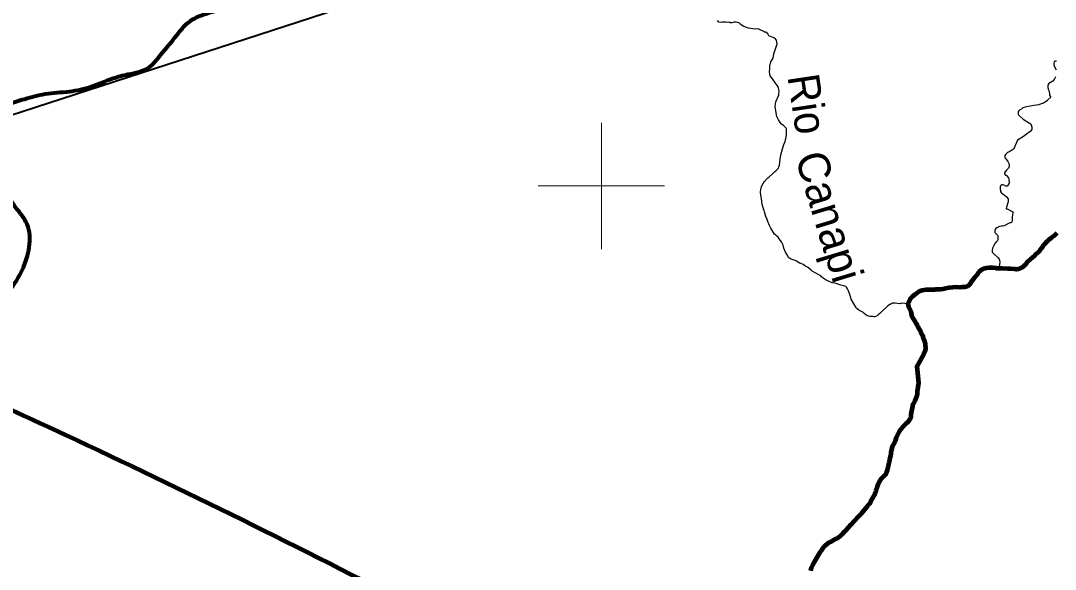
# Model space of a CAD drawing. Extents: x 553962 to 842807, y 8883888 to 9032388.
# Drawn here: x 640806 to 657184, y 8968932 to 8977616 of the extents above; entities that cross this region are included whole.
import ezdxf
from ezdxf.enums import TextEntityAlignment as Align

# ---------------------------------------------------------------- set-up
doc = ezdxf.new("R2010")
doc.units = 0
doc.header["$LTSCALE"] = 200
for name, color, linetype, lineweight in [('12', 7, 'Continuous', 25), ('2', 7, 'Continuous', 13), ('24', 7, 'Continuous', 25), ('50', 7, 'Continuous', 80), ('9', 7, 'Continuous', 90)]:
    doc.layers.add(name, color=color, linetype=linetype, lineweight=lineweight)
doc.layers.add('49', color=7, linetype='Continuous')

msp = doc.modelspace()

# ---------------------------------------------------------------- linework, layer by layer
at = {"layer": '12', "lineweight": 40}
msp.add_line((636526.5, 8974783.6), (662912, 8983353), dxfattribs=at)
at = {"layer": '2'}
for p, q in [((650000, 8974000), (650000, 8976000)), ((649000, 8975000), (651000, 8975000))]:
    msp.add_line(p, q, dxfattribs=at)
at = {"layer": '24'}
for p, q in [((655116.6, 8973422.7), (655117, 8973424.3)), ((654851.3, 8973132), (654755.7, 8973142.7))]:
    msp.add_line(p, q, dxfattribs=at)
for points in [[(652771.6, 8977307.6), (652743.6, 8977336.7), (652700, 8977355.6), (652648.8, 8977376.5), (652631.7, 8977406.9), (652599.1, 8977434.4), (652582.3, 8977435.4), (652567.8, 8977444.9), (652514, 8977471.5), (652479.8, 8977484.8), (652430.5, 8977481), (652391.1, 8977486.8), (652363.3, 8977492), (652326.1, 8977499.9), (652255.9, 8977522.7), (652202.8, 8977555), (652189.5, 8977577.8), (652130.7, 8977591.1), (652098.4, 8977593), (652062.3, 8977583.5), (652039.6, 8977583.5), (652020.6, 8977593), (651997.8, 8977587.3), (651961.8, 8977593), (651916.2, 8977594.9), (651899.2, 8977589.2), (651855.5, 8977591.1), (651834.4, 8977616.2)], [(652799.8, 8975280.4), (652809.8, 8975302.2), (652816.1, 8975328.3), (652822.4, 8975374.6), (652826.9, 8975422.5), (652839.8, 8975493.2), (652864.5, 8975587.5), (652888.2, 8975655.6), (652908, 8975704.5), (652925.9, 8975773.4), (652929.4, 8975820.5), (652930.5, 8975902.1), (652923, 8975914.4), (652902.1, 8975937.5), (652881.4, 8975957.1), (652852.2, 8975978.9), (652827.9, 8976005.5), (652801.9, 8976045.7), (652783.3, 8976090.1), (652777.5, 8976093.8), (652748.7, 8976257.8), (652752.2, 8976297.8), (652759.6, 8976332.9), (652774.2, 8976369.2), (652784.3, 8976387.2), (652805.5, 8976443.3), (652809.5, 8976460.7), (652811.3, 8976493), (652801.1, 8976555.8), (652798.8, 8976558), (652796.5, 8976566.6), (652771.4, 8976603.6), (652757.2, 8976628.1), (652709.4, 8976696.7), (652669.3, 8976741.1), (652663.9, 8976773), (652657.8, 8976807.6), (652663.9, 8976859.5), (652664.9, 8976895.8), (652682.2, 8976964.3), (652718.6, 8977021.2), (652730, 8977089.5), (652778.6, 8977249)], [(652778.6, 8977249), (652777.9, 8977274.4), (652771.6, 8977307.6)], [(657200.6, 8976974.4), (657181.2, 8976975.7), (657176.4, 8976974.4), (657164.7, 8976965.5), (657159.4, 8976934.9), (657159.4, 8976922.3), (657172.8, 8976885.3), (657195, 8976838.1)], [(657133.7, 8976651.6), (657080.2, 8976620), (657066.2, 8976597.4), (657063.1, 8976576.8), (657066.3, 8976556.2), (657072.5, 8976533.5), (657080.9, 8976509.9), (657090.5, 8976462.8), (657091, 8976439.3), (657110, 8976410.1), (657110.9, 8976406.4), (657067.4, 8976361), (657056.2, 8976354.8), (657053.5, 8976348.9), (657031.1, 8976329.9), (657013.6, 8976321.3), (656995.6, 8976309.4), (656979.2, 8976303.3), (656959.2, 8976299.6), (656920.6, 8976285.8), (656884.5, 8976276.8), (656845.1, 8976271.2), (656729.4, 8976250.9), (656707.8, 8976249), (656672.3, 8976234.3), (656651.5, 8976222.8), (656618, 8976199.7), (656600.5, 8976181.9), (656595.8, 8976166.3), (656594.8, 8976146.6), (656595.7, 8976138.4), (656602.4, 8976126.5), (656615.7, 8976111), (656677.7, 8976057.2), (656776.5, 8975994.6), (656782.5, 8975993.7), (656799.6, 8975973.9), (656803.7, 8975967.1), (656814.1, 8975929.4), (656813.1, 8975895.9), (656791.5, 8975865.6), (656785.6, 8975862.2), (656783.8, 8975858), (656775.5, 8975856.3), (656772.4, 8975851.8), (656742.2, 8975832.4), (656721.1, 8975813.8), (656679, 8975783.2), (656609.4, 8975739.2), (656588, 8975723), (656553.5, 8975648.5), (656550.6, 8975639.1), (656544.7, 8975630.5), (656542.4, 8975621.5), (656520.2, 8975584), (656507.8, 8975571.5), (656503.7, 8975569.7), (656500.5, 8975566.2), (656496.9, 8975565.1), (656495.3, 8975562.1), (656486.8, 8975559.7), (656479.1, 8975553.8), (656468.9, 8975552.5), (656445.8, 8975536.4), (656445.8, 8975536.4)], [(657185.6, 8976725.5), (657177.3, 8976704.9), (657165.5, 8976683.5), (657144.4, 8976659), (657138.5, 8976657.5), (657133.7, 8976651.6)], [(656445.8, 8975536.4), (656428.1, 8975527.1), (656412.7, 8975513.8), (656400.9, 8975501.1), (656386.7, 8975481.1), (656383.9, 8975464.5), (656385.2, 8975443.3), (656398.8, 8975427.1), (656422.7, 8975403.9), (656434, 8975387.3), (656444.5, 8975366.6), (656451.2, 8975343.8), (656452.2, 8975307.7), (656444.4, 8975279.3), (656420.2, 8975258.8), (656406.9, 8975244.3), (656382, 8975208.4), (656379.8, 8975191.2), (656391.2, 8975173.8), (656397, 8975172), (656400.5, 8975168.9), (656408.8, 8975165.1), (656442.9, 8975127.3), (656450.2, 8975105.1), (656451, 8975049), (656444.2, 8975024.3), (656423.6, 8974996.6), (656411.6, 8974995.5), (656402.2, 8974996.5), (656392.2, 8975002.6), (656384.2, 8975004.6), (656371.7, 8975013.2), (656353.6, 8975017.8), (656334.6, 8975017.5), (656320.6, 8975007.7), (656317.6, 8975003.5), (656311.8, 8974985.1)], [(654755.7, 8973142.7), (654720.6, 8973132.1), (654647.5, 8973144.9), (654604.9, 8973142), (654598.8, 8973140.5), (654534.6, 8973104.9), (654437.3, 8973012.6), (654419.5, 8972998.8), (654403.8, 8972979.2), (654381.6, 8972957.8), (654363, 8972946.1), (654335.2, 8972931.4), (654326.4, 8972929.3), (654308.8, 8972928.4), (654287.9, 8972933.5), (654250.2, 8972934.8), (654229.3, 8972940.7), (654192.4, 8972956.2), (654152.5, 8972986.8), (654147.8, 8972992.5), (654142.1, 8972995.3), (654139, 8973001.3), (654076, 8973035.9), (654041.5, 8973060), (654027.3, 8973074.1), (654028.3, 8973079.5), (653955, 8973206), (653948.8, 8973231.1), (653931.5, 8973279.1), (653918, 8973324.5), (653906.3, 8973348.1), (653892.5, 8973371.7), (653880.9, 8973398.6), (653873.4, 8973402.2), (653869.2, 8973406.6), (653838.8, 8973418.7), (653790.9, 8973428.7), (653697.5, 8973459.4), (653649.6, 8973468.4), (653604, 8973484.9), (653582.4, 8973495.6), (653556.1, 8973510.9), (653509.5, 8973541.4), (653482.9, 8973561.9), (653470.5, 8973577.6), (653442.6, 8973592.3), (653395.4, 8973620.1), (653335.2, 8973650.9), (653328.8, 8973657.6), (653317.1, 8973665.3), (653282.9, 8973700.4), (653261.2, 8973715), (653237, 8973727.3), (653213.3, 8973743.3), (653191.4, 8973755.3), (653143.5, 8973777.1), (653134.4, 8973779.3), (653111.9, 8973795.2), (653085.1, 8973811.8), (653065.5, 8973821.4), (653019.2, 8973837.3), (653002.9, 8973840.6), (652981, 8973851.6), (652965.9, 8973864.6), (652937, 8973909.3), (652911.1, 8973953), (652887.5, 8974017.3), (652874.5, 8974060.1), (652864.8, 8974083.7), (652850.2, 8974112.8), (652813.3, 8974163.9), (652794.5, 8974187.8), (652771, 8974210.2), (652753.5, 8974223.6), (652741.1, 8974236.2), (652681.1, 8974329.2), (652660, 8974375.6), (652651, 8974399.9), (652639.3, 8974423.5), (652623.5, 8974469.8), (652603.2, 8974516.9), (652579.3, 8974588.4), (652572.8, 8974612), (652562.8, 8974637.3), (652546.2, 8974706.2), (652532.2, 8974799.6), (652526.8, 8974824.9), (652519.2, 8974897.6), (652518.3, 8974918.3), (652521.3, 8974941), (652527.4, 8974967.1), (652535.4, 8974989), (652558, 8975036.1), (652577.2, 8975063.9), (652631.7, 8975125.9), (652648.1, 8975141.2), (652704.5, 8975187.2), (652741, 8975221.5), (652762.8, 8975244.2), (652783.3, 8975259.7), (652799.8, 8975280.4)], [(656311.8, 8974985.1), (656309.9, 8974965.4), (656310.9, 8974936.3), (656314.2, 8974931), (656318.5, 8974912), (656333.2, 8974887.1), (656339.6, 8974883.1), (656344.1, 8974878.5), (656345.9, 8974874.7), (656352.9, 8974872.7), (656357, 8974868.2), (656372.6, 8974857.7), (656410.2, 8974827.3), (656435.2, 8974796.3), (656440.2, 8974762.4), (656440.3, 8974749.1), (656410.3, 8974666), (656407.6, 8974643.7), (656410, 8974639.2), (656419.4, 8974636), (656511, 8974591.7), (656507.5, 8974524.4), (656501.5, 8974515), (656499.2, 8974456.9), (656494.7, 8974426.9), (656479.6, 8974416.5), (656466.4, 8974413.5), (656443.7, 8974405.2), (656396.6, 8974380.7), (656373, 8974370.1), (656349.5, 8974365.7), (656325.9, 8974363.3), (656300.7, 8974356.3), (656256.1, 8974338), (656235.1, 8974319.4), (656224.5, 8974294.9), (656226, 8974270.5), (656228.6, 8974263.7), (656258.3, 8974232.1), (656265, 8974227.3), (656269.2, 8974222.2), (656273.4, 8974202.8), (656276.5, 8974180.1), (656276.6, 8974148.4), (656268.5, 8974134.2), (656264, 8974130.4), (656262.3, 8974125), (656257.6, 8974123.2), (656253.4, 8974116.8), (656244.1, 8974109.9), (656235.6, 8974096.1), (656229.8, 8974092), (656209.8, 8974056.4), (656189, 8974012.7), (656183.6, 8973985.6), (656184.6, 8973963), (656186.9, 8973950), (656191.3, 8973947.8), (656199.2, 8973934.2), (656213.7, 8973918.7), (656274.2, 8973865.6), (656294.1, 8973843.5), (656302.2, 8973822.7), (656307.8, 8973793.6), (656289.8, 8973694.9)]]:
    msp.add_lwpolyline(points, dxfattribs=at)
at = {"layer": '24', "lineweight": 53}
for points in [[(657210.5, 8974250), (657181.7, 8974226.4), (657161.9, 8974207.7), (657140, 8974192), (657118.9, 8974173.4), (657078.2, 8974140.8), (657056.3, 8974119.3), (657035, 8974103.2), (657016, 8974086.2), (656999.6, 8974063.5), (656982.9, 8974036.6), (656963.3, 8974017.4), (656946, 8973988.7), (656926.4, 8973964.7), (656902.1, 8973940.5), (656874.4, 8973917.8), (656856.7, 8973895.3), (656791.9, 8973840.8)], [(656791.9, 8973840.8), (656791.8, 8973840.8), (656728.6, 8973781.9), (656729.8, 8973775.9), (656716.7, 8973763.4), (656647.1, 8973704.9), (656615.1, 8973689.9), (656598.4, 8973684.2), (656598.4, 8973684.2), (656567.2, 8973679.3), (656556.3, 8973683.2), (656536.3, 8973682.5), (656475.8, 8973689.6), (656432.2, 8973686.7), (656347.3, 8973694), (656260.8, 8973695.2), (656240.2, 8973697.3)], [(656240.2, 8973697.3), (656197.4, 8973704.6), (656175.9, 8973703.8), (656133.1, 8973704.7), (656090.3, 8973699.3), (656067.2, 8973694.6), (656047.4, 8973688.6), (656026.8, 8973679.3), (655983.7, 8973648.4), (655968.2, 8973630.5), (655940.3, 8973590.2), (655926.4, 8973572.3), (655907.2, 8973551.6), (655857.4, 8973488), (655825.2, 8973435), (655819.5, 8973432.4), (655817.1, 8973428.1), (655813, 8973426.4), (655807.3, 8973421.2), (655797.6, 8973417.6), (655794, 8973413), (655766.8, 8973403.9), (655745.4, 8973399.7), (655722.2, 8973400.4), (655702.5, 8973398.4), (655680.3, 8973394.3), (655616.9, 8973396.2), (655501.2, 8973386.6), (655443.3, 8973378), (655404.8, 8973367.5), (655366.2, 8973362.1), (655326.8, 8973361.9), (655289.1, 8973358.7), (655269, 8973355.7), (655249.7, 8973356.6), (655212, 8973355.5), (655191.9, 8973353.5), (655154.1, 8973354.5), (655137.5, 8973353.6), (655077.8, 8973346), (655060.3, 8973342.2), (655039.3, 8973335.4), (655029.9, 8973329.2), (655023.6, 8973328.5), (655016.9, 8973321.8), (654963.5, 8973284.3), (654916.4, 8973246.2), (654900.8, 8973228.3), (654881.6, 8973201), (654851.3, 8973132), (654852.3, 8973113.8), (654858.7, 8973088.2), (654878.1, 8973056.9), (654895, 8973014.3), (654909.2, 8972953.2), (654915.3, 8972934.7), (654923.6, 8972916.2), (654947.3, 8972875.3), (654982.1, 8972819.3), (654996.2, 8972794.1), (655005.3, 8972774), (655014.6, 8972757.2), (655044.4, 8972710.5), (655053.7, 8972692), (655056.5, 8972676.5), (655080.1, 8972632.6), (655093.2, 8972594.1), (655109.8, 8972556.3), (655111.9, 8972544), (655121.8, 8972516.9), (655124, 8972498.5), (655124.2, 8972478.4), (655127.3, 8972439.8), (655123.7, 8972391.1), (655118.2, 8972380.4), (655102.9, 8972341.9), (654992.2, 8972144.1), (655019.8, 8971884.2), (654998.6, 8971745.3), (654995, 8971695.3), (654989.7, 8971685.4), (654957.7, 8971597.4), (654937.6, 8971556.5), (654925.2, 8971519.5), (654918.6, 8971481), (654907, 8971442.4), (654896.1, 8971382.9), (654895.8, 8971344.4), (654892, 8971324.4), (654883.1, 8971306.7), (654872.7, 8971291.8), (654840.1, 8971251.1), (654818.4, 8971232.1), (654818.4, 8971232.1), (654777.1, 8971189.8), (654713.1, 8971114), (654675.8, 8971041.8), (654665.8, 8971017.4), (654650.1, 8970966.2), (654641.7, 8970946), (654616.5, 8970899.6)], [(654616.5, 8970899.6), (654597.8, 8970850.8), (654585.3, 8970804.5), (654581.2, 8970781.8), (654578.8, 8970758.3), (654572.6, 8970734.7), (654560.7, 8970664), (654554.4, 8970640.4), (654550, 8970616.9), (654542.2, 8970591.6), (654533, 8970547), (654526.8, 8970523.4), (654524.2, 8970501.2), (654508.2, 8970458.4), (654499, 8970437.8), (654493.5, 8970429), (654477.7, 8970417.1), (654443, 8970382.2), (654421.1, 8970358.3), (654389.5, 8970306.2), (654379.5, 8970284), (654365, 8970242.8), (654351.1, 8970197.8), (654345.4, 8970173.5), (654336.8, 8970149.9), (654324.7, 8970123.6), (654288, 8970056.4), (654272.8, 8970031.9), (654254.6, 8969979.6), (654230.2, 8969960.2), (654218.1, 8969945.2), (654200.3, 8969917.9), (654115.1, 8969812.6), (654066, 8969768.5), (653998.5, 8969693.6), (653949.1, 8969634.7), (653875.5, 8969551.6), (653848.1, 8969526.1), (653826.1, 8969509.2), (653807.7, 8969485.9), (653788.8, 8969465.8), (653781.7, 8969461.6), (653774.9, 8969453.3), (653733.8, 8969425.9), (653708.2, 8969413.9), (653656.8, 8969380.9), (653631.1, 8969367), (653605.4, 8969356.1), (653579.7, 8969340.1), (653534.3, 8969303.2), (653514.9, 8969279.7), (653477.3, 8969225.2), (653456.6, 8969199.3), (653405, 8969106.7), (653344.1, 8969008.1), (653319.5, 8968956.7), (653307.6, 8968905.3)]]:
    msp.add_lwpolyline(points, dxfattribs=at)
at = {"layer": '50'}
msp.add_spline([(639219.5, 8972216.9), (639452.6, 8972345.4), (639566.1, 8972552.1), (639684.3, 8972733.3), (640073.1, 8972839), (640280.5, 8972922.2), (640428.6, 8973082.5), (640849.7, 8973711.5), (640889.8, 8974432.9), (640746.7, 8974633.5), (640599.2, 8974885), (640542.2, 8975124.8), (640537.6, 8975526.6), (640547.2, 8975862.1), (640623.3, 8976272.7), (640866.2, 8976375.7), (641194.3, 8976456.9), (641577.1, 8976496.6), (641925.3, 8976572.4), (642269.1, 8976704.3), (642501.4, 8976766.7), (642840, 8976878.3), (642993.1, 8977038.6), (643248.9, 8977349.8), (643488.9, 8977610.4), (643777.4, 8977738), (644100.5, 8977824.4), (644651.3, 8978008.9), (645197.8, 8978239.2), (645476.7, 8978402.6), (645653.3, 8978806.6), (645865.1, 8979215.1), (646221.3, 8979509.5), (646615.8, 8979665.9), (646766.4, 8979643.2), (647093, 8979617.7), (647304.4, 8979624.5), (647500.7, 8979631.6), (647581.3, 8979640.5), (647811.6, 8979776.6)], degree=3, dxfattribs=at)
at = {"layer": '9'}
for points in [[(657210.5, 8974250), (657181.7, 8974226.4), (657161.9, 8974207.7), (657140, 8974192), (657118.9, 8974173.4), (657078.2, 8974140.8), (657056.3, 8974119.3), (657035, 8974103.2), (657016, 8974086.2), (656999.6, 8974063.5), (656982.9, 8974036.6), (656963.3, 8974017.4), (656946, 8973988.7), (656926.4, 8973964.7), (656902.1, 8973940.5), (656874.4, 8973917.8), (656856.7, 8973895.3), (656791.9, 8973840.8)], [(656791.9, 8973840.8), (656791.8, 8973840.8), (656728.6, 8973781.9), (656729.8, 8973775.9), (656716.7, 8973763.4), (656647.1, 8973704.9), (656615.1, 8973689.9), (656598.4, 8973684.2), (656598.4, 8973684.2), (656567.2, 8973679.3), (656556.3, 8973683.2), (656536.3, 8973682.5), (656475.8, 8973689.6), (656432.2, 8973686.7), (656347.3, 8973694), (656260.8, 8973695.2), (656240.2, 8973697.3)], [(656240.2, 8973697.3), (656197.4, 8973704.6), (656175.9, 8973703.8), (656133.1, 8973704.7), (656090.3, 8973699.3), (656067.2, 8973694.6), (656047.4, 8973688.6), (656026.8, 8973679.3), (655983.7, 8973648.4), (655968.2, 8973630.5), (655940.3, 8973590.2), (655926.4, 8973572.3), (655907.2, 8973551.6), (655857.4, 8973488), (655825.2, 8973435), (655819.5, 8973432.4), (655817.1, 8973428.1), (655813, 8973426.4), (655807.3, 8973421.2), (655797.6, 8973417.6), (655794, 8973413), (655766.8, 8973403.9), (655745.4, 8973399.7), (655722.2, 8973400.4), (655702.5, 8973398.4), (655680.3, 8973394.3), (655616.9, 8973396.2), (655501.2, 8973386.6), (655443.3, 8973378), (655404.8, 8973367.5), (655366.2, 8973362.1), (655326.8, 8973361.9), (655289.1, 8973358.7), (655269, 8973355.7), (655249.7, 8973356.6), (655212, 8973355.5), (655191.9, 8973353.5), (655154.1, 8973354.5), (655137.5, 8973353.6), (655077.8, 8973346), (655060.3, 8973342.2), (655039.3, 8973335.4), (655029.9, 8973329.2), (655023.6, 8973328.5), (655016.9, 8973321.8), (654963.5, 8973284.3), (654916.4, 8973246.2), (654900.8, 8973228.3), (654881.6, 8973201), (654851.3, 8973132), (654852.3, 8973113.8), (654858.7, 8973088.2), (654878.1, 8973056.9), (654895, 8973014.3), (654909.2, 8972953.2), (654915.3, 8972934.7), (654923.6, 8972916.2), (654947.3, 8972875.3), (654982.1, 8972819.3), (654996.2, 8972794.1), (655005.3, 8972774), (655014.6, 8972757.2), (655044.4, 8972710.5), (655053.7, 8972692), (655056.5, 8972676.5), (655080.1, 8972632.6), (655093.2, 8972594.1), (655109.8, 8972556.3), (655111.9, 8972544), (655121.8, 8972516.9), (655124, 8972498.5), (655124.2, 8972478.4), (655127.3, 8972439.8), (655123.7, 8972391.1), (655118.2, 8972380.4), (655102.9, 8972341.9), (654992.2, 8972144.1), (655019.8, 8971884.2), (654998.6, 8971745.3), (654995, 8971695.3), (654989.7, 8971685.4), (654957.7, 8971597.4), (654937.6, 8971556.5), (654925.2, 8971519.5), (654918.6, 8971481), (654907, 8971442.4), (654896.1, 8971382.9), (654895.8, 8971344.4), (654892, 8971324.4), (654883.1, 8971306.7), (654872.7, 8971291.8), (654840.1, 8971251.1), (654818.4, 8971232.1), (654818.4, 8971232.1), (654777.1, 8971189.8), (654713.1, 8971114), (654675.8, 8971041.8), (654665.8, 8971017.4), (654650.1, 8970966.2), (654641.7, 8970946), (654616.5, 8970899.6)], [(654616.5, 8970899.6), (654597.8, 8970850.8), (654585.3, 8970804.5), (654581.2, 8970781.8), (654578.8, 8970758.3), (654572.6, 8970734.7), (654560.7, 8970664), (654554.4, 8970640.4), (654550, 8970616.9), (654542.2, 8970591.6), (654533, 8970547), (654526.8, 8970523.4), (654524.2, 8970501.2), (654508.2, 8970458.4), (654499, 8970437.8), (654493.5, 8970429), (654477.7, 8970417.1), (654443, 8970382.2), (654421.1, 8970358.3), (654389.5, 8970306.2), (654379.5, 8970284), (654365, 8970242.8), (654351.1, 8970197.8), (654345.4, 8970173.5), (654336.8, 8970149.9), (654324.7, 8970123.6), (654288, 8970056.4), (654272.8, 8970031.9), (654254.6, 8969979.6), (654230.2, 8969960.2), (654218.1, 8969945.2), (654200.3, 8969917.9), (654115.1, 8969812.6), (654066, 8969768.5), (653998.5, 8969693.6), (653949.1, 8969634.7), (653875.5, 8969551.6), (653848.1, 8969526.1), (653826.1, 8969509.2), (653807.7, 8969485.9), (653788.8, 8969465.8), (653781.7, 8969461.6), (653774.9, 8969453.3), (653733.8, 8969425.9), (653708.2, 8969413.9), (653656.8, 8969380.9), (653631.1, 8969367), (653605.4, 8969356.1), (653579.7, 8969340.1), (653534.3, 8969303.2), (653514.9, 8969279.7), (653477.3, 8969225.2), (653456.6, 8969199.3), (653405, 8969106.7), (653344.1, 8969008.1), (653319.5, 8968956.7), (653307.6, 8968905.3)]]:
    msp.add_lwpolyline(points, dxfattribs=at)
msp.add_spline([(637260.6, 8972975.8), (641524.5, 8971056.2), (652526.1, 8965412.7), (653164.3, 8965062.8), (670790.5, 8953770.1), (686194, 8943929.9), (696283.3, 8937647.1)], degree=3, dxfattribs=at)

# ---------------------------------------------------------------- texts
at = {"layer": '49', "width": 0.95}
msp.add_text('Rio', height=500, rotation=278.527, dxfattribs=at).set_placement((653013, 8976261.9), align=Align.CENTER)
at = {"layer": '49'}
msp.add_text('Canapi', height=500, rotation=286.879, dxfattribs=at).set_placement((653368, 8974444.7), align=Align.CENTER)

doc.saveas('drawing.dxf')
